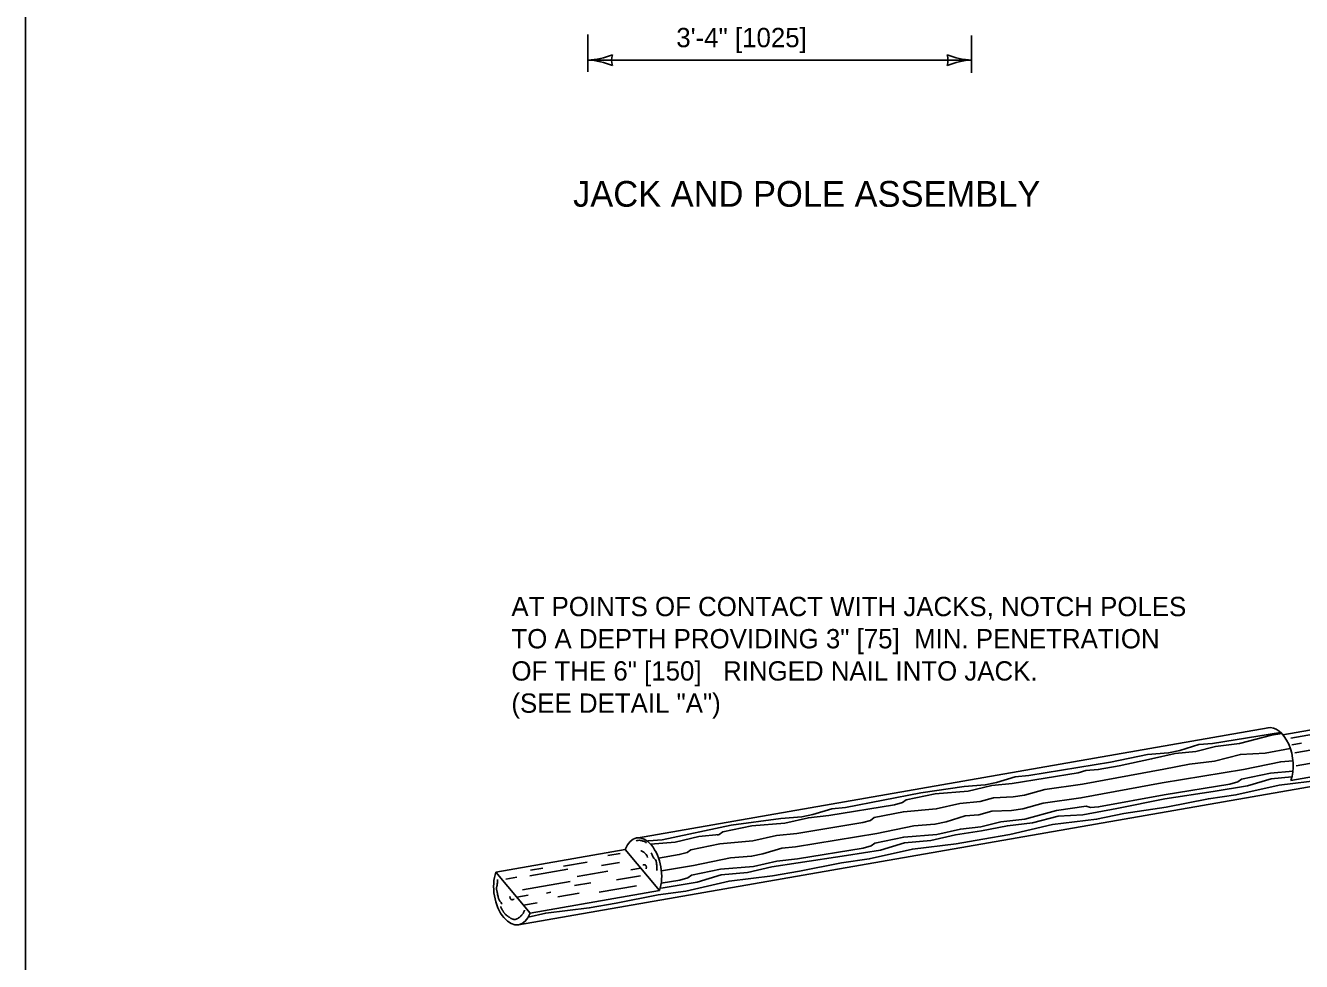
# Model space of a CAD drawing. Extents: x 49991.4 to 50021, y 49987.6 to 50011.4.
# Drawn here: x 49999.384 to 50003.345, y 49992.829 to 49995.736 of the extents above; entities that cross this region are included whole.
import ezdxf

# ---------------------------------------------------------------- set-up
doc = ezdxf.new("R2010")
doc.units = 0
for name, color, linetype in [('Level 1', 7, 'Continuous'), ('Level 2', 7, 'Continuous'), ('Level 3', 7, 'Continuous')]:
    doc.layers.add(name, color=color, linetype=linetype)

msp = doc.modelspace()

# ---------------------------------------------------------------- linework, layer by layer
at = {"layer": 'Level 1'}
for p, q in [((50000.9144, 49992.9433), (50005.951, 49993.8227)), ((50001.2805, 49993.2127), (50003.2413, 49993.5553)), ((50003.4416, 49993.5605), (50003.2869, 49993.5335)), ((50003.4436, 49993.5457), (50003.3119, 49993.5226)), ((50003.3445, 49993.5076), (50003.3151, 49993.5025)), ((50003.4314, 49993.4959), (50003.3243, 49993.4772)), ((50003.4907, 49993.465), (50003.3277, 49993.4365)), ((50003.3119, 49993.3918), (50003.5478, 49993.433)), ((50000.8437, 49993.1066), (50001.245, 49993.1767)), ((50001.1914, 49993.158), (50001.2291, 49993.1646)), ((50001.245, 49993.1767), (50001.3514, 49993.0498)), ((50000.95, 49992.9796), (50000.8437, 49993.1066)), ((50000.9494, 49993.095), (50001.0674, 49993.1157)), ((50000.9513, 49993.1127), (50000.989, 49993.1193)), ((50001.0541, 49993.1252), (50001.1266, 49993.1379)), ((50001.0961, 49993.0928), (50001.1908, 49993.1093)), ((50001.1716, 49993.1269), (50001.227, 49993.1366)), ((50001.2624, 49993.1142), (50001.2929, 49993.1196)), ((50000.875, 49993.0854), (50000.9089, 49993.0913)), ((50000.9265, 49993.052), (50001.0743, 49993.078)), ((50001.0879, 49993.065), (50001.1382, 49993.0739)), ((50001.1645, 49993.0441), (50001.2802, 49993.0644)), ((50001.2184, 49993.0824), (50001.2923, 49993.0953)), ((50000.9089, 49993.0287), (50000.9438, 49993.0349)), ((50000.95, 49992.9796), (50001.3514, 49993.0498)), ((50001.0007, 49993.0418), (50001.0141, 49993.0442)), ((50001.0358, 49993.03), (50001.1024, 49993.0416)), ((50000.9298, 49993.0037), (50000.9714, 49993.0111))]:
    msp.add_line(p, q, dxfattribs=at)
msp.add_lwpolyline([(49999.3835, 49998.9992), (50016.7501, 49998.9992), (50016.7501, 49987.7988), (49999.3835, 49987.7988)], close=True, dxfattribs=at)
for points in [[(50003.2838, 49993.5369), (50003.2516, 49993.5324), (50003.1525, 49993.5058), (50003.0779, 49993.4967), (50003.0162, 49993.4813)], [(50003.0681, 49993.5059), (50003.2799, 49993.5408)], [(50002.4987, 49993.4065), (50002.7518, 49993.4483), (50002.8669, 49993.4722), (50002.9323, 49993.4772), (50002.967, 49993.4845), (50003.0258, 49993.5026), (50003.0681, 49993.5059)], [(50002.4467, 49993.3818), (50002.651, 49993.4155), (50002.6756, 49993.4224), (50002.7135, 49993.4251), (50002.7782, 49993.437), (50002.8795, 49993.4581), (50002.9527, 49993.4748), (50003.0162, 49993.4813)], [(50003.31, 49993.4909), (50003.2317, 49993.4763), (50003.1549, 49993.4722), (50003.0748, 49993.4514), (50002.9975, 49993.4418), (50002.917, 49993.426)], [(50002.917, 49993.426), (50002.6647, 49993.3795), (50002.548, 49993.363), (50002.4851, 49993.3455), (50002.4499, 49993.3407), (50002.3886, 49993.3377), (50002.3476, 49993.3265)], [(50002.912, 49993.3838), (50003.1651, 49993.4257), (50003.2803, 49993.4497), (50003.3182, 49993.4525)], [(50002.9184, 49993.3468), (50003.1227, 49993.3804), (50003.1473, 49993.3873), (50003.1588, 49993.3958), (50003.2489, 49993.4143), (50003.3182, 49993.4202)], [(50001.8772, 49993.2823), (50002.0815, 49993.3161), (50002.1061, 49993.3229), (50002.1176, 49993.3314), (50002.2077, 49993.3499), (50002.31, 49993.3585), (50002.3833, 49993.3753), (50002.4467, 49993.3818)], [(50001.9293, 49993.307), (50002.1631, 49993.3529), (50002.2976, 49993.3728), (50002.3629, 49993.3777), (50002.3976, 49993.385), (50002.4563, 49993.4032), (50002.4987, 49993.4065)], [(50002.912, 49993.3838), (50002.6597, 49993.3373), (50002.5431, 49993.3209), (50002.4801, 49993.3034), (50002.4449, 49993.2986), (50002.3836, 49993.2957), (50002.3426, 49993.2843)], [(50002.9206, 49993.3342), (50003.0707, 49993.3569), (50003.1769, 49993.3744), (50003.2506, 49993.3965), (50003.3152, 49993.4024)], [(50002.925, 49993.3087), (50003.0558, 49993.3348), (50003.1413, 49993.3467), (50003.2756, 49993.3771), (50003.4108, 49993.3937), (50003.4943, 49993.4082)], [(50002.9184, 49993.3468), (50002.7149, 49993.3092), (50002.6893, 49993.3073), (50002.6758, 49993.3115), (50002.5846, 49993.2983), (50002.4856, 49993.2717), (50002.4109, 49993.2626), (50002.3491, 49993.2473)], [(50001.3598, 49993.2075), (50001.5737, 49993.2524), (50001.7281, 49993.2733), (50001.7935, 49993.2783), (50001.8281, 49993.2856), (50001.8868, 49993.3036), (50001.9293, 49993.307)], [(50001.7782, 49993.2269), (50001.9824, 49993.2608), (50002.0071, 49993.2675), (50002.0185, 49993.2761), (50002.1087, 49993.2945), (50002.2109, 49993.3031), (50002.2842, 49993.3199), (50002.3476, 49993.3265)], [(50002.9206, 49993.3342), (50002.7718, 49993.3048), (50002.666, 49993.2851), (50002.5891, 49993.281), (50002.5092, 49993.2601), (50002.4317, 49993.2506), (50002.3513, 49993.2347)], [(50002.925, 49993.3087), (50002.7932, 49993.289), (50002.7086, 49993.2711), (50002.5721, 49993.2543), (50002.4393, 49993.224), (50002.3557, 49993.2094)], [(50001.5305, 49993.2217), (50001.5368, 49993.2234), (50001.5482, 49993.232), (50001.6383, 49993.2504), (50001.7405, 49993.259), (50001.8139, 49993.2758), (50001.8772, 49993.2823)], [(50001.7734, 49993.1849), (50002.0263, 49993.2266), (50002.1416, 49993.2507), (50002.2069, 49993.2557), (50002.2416, 49993.263), (50002.3003, 49993.2811), (50002.3426, 49993.2843)], [(50001.3238, 49993.1938), (50001.4001, 49993.2002), (50001.4734, 49993.217), (50001.5368, 49993.2234)], [(50001.3485, 49993.1506), (50001.4129, 49993.1612), (50001.4375, 49993.168), (50001.449, 49993.1765), (50001.5392, 49993.1951), (50001.6414, 49993.2037), (50001.7148, 49993.2204), (50001.7782, 49993.2269)], [(50001.7798, 49993.1478), (50001.9839, 49993.1814), (50002.0086, 49993.1884), (50002.0199, 49993.197), (50002.1101, 49993.2154), (50002.2124, 49993.224), (50002.2858, 49993.2407), (50002.3491, 49993.2473)], [(50001.7819, 49993.1353), (50001.9318, 49993.1581), (50002.0381, 49993.1752), (50002.1119, 49993.1975), (50002.1941, 49993.2052), (50002.2703, 49993.2224), (50002.3513, 49993.2347)], [(50001.3136, 49993.2031), (50001.3174, 49993.2042), (50001.3598, 49993.2075)], [(50001.3575, 49993.1107), (50001.457, 49993.1272), (50001.5723, 49993.1513), (50001.6376, 49993.1561), (50001.6723, 49993.1636), (50001.731, 49993.1816), (50001.7734, 49993.1849)], [(50001.7863, 49993.1099), (50001.917, 49993.1359), (50002.0027, 49993.1476), (50002.137, 49993.1782), (50002.2722, 49993.1947), (50002.3557, 49993.2094)], [(50001.3569, 49993.0725), (50001.4146, 49993.0821), (50001.4392, 49993.0889), (50001.4507, 49993.0974), (50001.5408, 49993.1158), (50001.6431, 49993.1246), (50001.7164, 49993.1412), (50001.7798, 49993.1478)], [(50001.217, 49993.0105), (50001.3478, 49993.0364), (50001.4334, 49993.0481), (50001.5676, 49993.0788), (50001.7027, 49993.0953), (50001.7863, 49993.1099)], [(50001.3537, 49993.0572), (50001.3626, 49993.0585), (50001.4688, 49993.0758), (50001.5426, 49993.0981), (50001.6247, 49993.1057), (50001.7009, 49993.1229), (50001.7819, 49993.1353)], [(50000.9442, 49992.967), (50000.9983, 49992.9794), (50001.1336, 49992.9959), (50001.217, 49993.0105)]]:
    msp.add_lwpolyline(points, dxfattribs=at)
for centre, start_param, end_param in [((50003.2587, 49993.4554), 3.925708, 6.306126), ((50001.2981, 49993.1129), 3.931522, 7.06353), ((50000.8969, 49993.0432), 0.785888, 3.92598)]:
    msp.add_ellipse(centre, major_axis=(-0.0175, 0.0999), ratio=0.577493, start_param=start_param, end_param=end_param, dxfattribs=at)
for points in [[(50001.3108, 49993.1975), (50001.3075, 49993.2008), (50001.2979, 49993.2039), (50001.2925, 49993.2054), (50001.2857, 49993.2053), (50001.2794, 49993.2043)], [(50001.2932, 49993.1732), (50001.2949, 49993.1725), (50001.3026, 49993.1688), (50001.3079, 49993.1635), (50001.3124, 49993.1589), (50001.3139, 49993.1527)], [(50001.3444, 49993.1115), (50001.3443, 49993.1117), (50001.3437, 49993.1247), (50001.3425, 49993.1315), (50001.3412, 49993.1415), (50001.3323, 49993.1529), (50001.3281, 49993.1625), (50001.3257, 49993.1668)], [(50001.3008, 49993.1286), (50001.3012, 49993.1289), (50001.3013, 49993.129), (50001.3014, 49993.1291), (50001.3015, 49993.1292), (50001.3017, 49993.1293), (50001.302, 49993.1295), (50001.3025, 49993.1297), (50001.3036, 49993.1297), (50001.3048, 49993.1296), (50001.3054, 49993.1295), (50001.3059, 49993.1293), (50001.3063, 49993.1292), (50001.3066, 49993.1291), (50001.3073, 49993.1289), (50001.308, 49993.1285), (50001.3084, 49993.1283), (50001.3085, 49993.1282), (50001.3087, 49993.128), (50001.3091, 49993.1277), (50001.3095, 49993.1272), (50001.3101, 49993.1264), (50001.3105, 49993.1255), (50001.3106, 49993.125), (50001.3107, 49993.1245), (50001.3108, 49993.1233), (50001.3108, 49993.1221), (50001.3108, 49993.1209), (50001.3107, 49993.1197), (50001.3107, 49993.119), (50001.3107, 49993.1183), (50001.3106, 49993.1175), (50001.3106, 49993.1168)], [(50000.849, 49993.0838), (50000.849, 49993.0801), (50000.8489, 49993.0782), (50000.8487, 49993.0764), (50000.848, 49993.0706), (50000.8472, 49993.0649), (50000.8467, 49993.0624), (50000.8461, 49993.0599), (50000.8455, 49993.0575), (50000.8454, 49993.0562), (50000.8453, 49993.0556), (50000.8453, 49993.0549), (50000.8456, 49993.0527), (50000.8462, 49993.0505), (50000.8469, 49993.0482), (50000.8473, 49993.0471), (50000.8475, 49993.046), (50000.8483, 49993.0419), (50000.849, 49993.0378), (50000.8504, 49993.0314), (50000.8512, 49993.0282), (50000.8516, 49993.0267), (50000.8521, 49993.0251), (50000.8539, 49993.021), (50000.8563, 49993.0171), (50000.8633, 49993.0069)], [(50000.8997, 49993.0235), (50000.8994, 49993.0231), (50000.8993, 49993.023), (50000.8993, 49993.0229), (50000.8992, 49993.0228), (50000.899, 49993.0225), (50000.8989, 49993.0223), (50000.8984, 49993.022), (50000.8974, 49993.0215), (50000.8962, 49993.0213), (50000.8956, 49993.0213), (50000.8951, 49993.0212), (50000.8947, 49993.0212), (50000.8943, 49993.0211), (50000.8936, 49993.0211), (50000.8928, 49993.0212), (50000.8924, 49993.0214), (50000.8922, 49993.0214), (50000.892, 49993.0215), (50000.8915, 49993.0218), (50000.891, 49993.022), (50000.8902, 49993.0226), (50000.8895, 49993.0234), (50000.8892, 49993.0238), (50000.889, 49993.0242), (50000.8885, 49993.0253), (50000.8881, 49993.0265), (50000.8878, 49993.0276), (50000.8874, 49993.0287), (50000.8872, 49993.0294), (50000.887, 49993.0301), (50000.8868, 49993.0308), (50000.8866, 49993.0315)], [(50000.8586, 49993.0002), (50000.8626, 49992.9915), (50000.8635, 49992.9897), (50000.8644, 49992.988), (50000.8654, 49992.9863), (50000.8664, 49992.9846), (50000.8678, 49992.9823), (50000.8693, 49992.9802), (50000.871, 49992.9782), (50000.8719, 49992.9772), (50000.8728, 49992.9762), (50000.8765, 49992.973), (50000.8805, 49992.9701), (50000.8829, 49992.9683), (50000.8855, 49992.9666), (50000.888, 49992.9649), (50000.8906, 49992.9633), (50000.8922, 49992.9625), (50000.8938, 49992.9617), (50000.8954, 49992.9611), (50000.8963, 49992.9608), (50000.8972, 49992.9605), (50000.8988, 49992.9601), (50000.9003, 49992.9599), (50000.9018, 49992.9598), (50000.9025, 49992.9599), (50000.9033, 49992.96), (50000.9053, 49992.9604), (50000.9072, 49992.961), (50000.9101, 49992.9622), (50000.911, 49992.9627), (50000.9127, 49992.9636), (50000.9144, 49992.9646), (50000.9175, 49992.9668), (50000.9188, 49992.968), (50000.92, 49992.9692), (50000.9225, 49992.9718), (50000.9235, 49992.9729), (50000.9246, 49992.9739), (50000.9266, 49992.9761), (50000.9285, 49992.9785), (50000.9298, 49992.9811), (50000.9314, 49992.9851), (50000.9328, 49992.9891)]]:
    msp.add_spline(points, degree=3, dxfattribs=at)
at = {"layer": 'Level 3'}
for p, q in [((50001.1295, 49995.7081), (50001.1295, 49995.5915)), ((50002.3207, 49995.7049), (50002.3207, 49995.5883)), ((50002.3207, 49995.6283), (50001.1295, 49995.6283))]:
    msp.add_line(p, q, dxfattribs=at)
for centre, radius, start, end in [((50001.118, 49995.861), 0.233, 272.8273, 292.0772), ((50001.2577, 49995.6283), 0.0548, 162.1388, 197.8612), ((50002.3298, 49995.8504), 0.2223, 247.456, 267.6395), ((50002.1924, 49995.6283), 0.0548, 342.1388, 17.8612), ((50001.1203, 49995.4062), 0.2223, 67.456, 87.6395), ((50002.3321, 49995.3956), 0.233, 92.8273, 112.0772)]:
    msp.add_arc(centre, radius, start, end, dxfattribs=at)

# ---------------------------------------------------------------- texts
at = {"layer": 'Level 2'}
for s, height, p in [('3\'-4" [1025]', 0.06, (50001.4038, 49995.6683)), ('JACK AND POLE ASSEMBLY', 0.08, (50001.0833, 49995.1729)), ('AT POINTS OF CONTACT WITH JACKS, NOTCH POLES', 0.06, (50000.8919, 49993.9016)), ('TO A DEPTH PROVIDING 3" [75]  MIN. PENETRATION', 0.06, (50000.8919, 49993.8016)), ('OF THE 6" [150]   RINGED NAIL INTO JACK.', 0.06, (50000.8919, 49993.7016)), ('(SEE DETAIL "A")', 0.06, (50000.8919, 49993.6016))]:
    msp.add_text(s, height=height, dxfattribs=at).set_placement(p)

doc.saveas('drawing.dxf')
